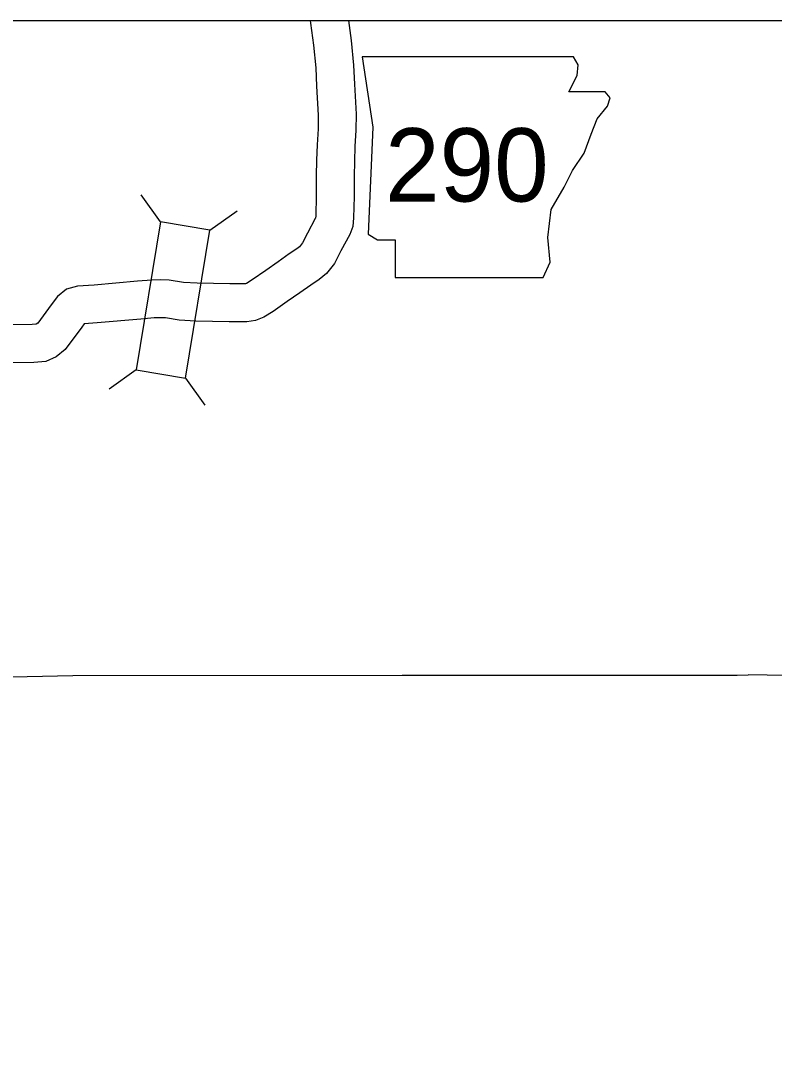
# Model space of a CAD drawing. Extents: x 1373862 to 1377080, y 1164775 to 1170415.
# Drawn here: x 1374349.9 to 1374409.6, y 1170307.2 to 1170388.8 of the extents above; entities that cross this region are included whole.
import ezdxf

# ---------------------------------------------------------------- set-up
doc = ezdxf.new("R2010")
doc.units = 0
doc.layers.add('1', color=7, linetype='Continuous')
doc.layers.add('Default', color=7, linetype='Continuous')

msp = doc.modelspace()

# ---------------------------------------------------------------- linework, layer by layer
at = {"layer": '1'}
msp.add_lwpolyline([(1373884.485, 1170388.771), (1374613.882, 1170388.771), (1374613.882, 1169861.944), (1373884.485, 1169861.944)], close=True, dxfattribs=at)
at = {"layer": 'Default'}
for p, q in [((1374361.035, 1170372.822), (1374359.499, 1170374.969)), ((1374364.942, 1170372.175), (1374367.089, 1170373.711)), ((1374359.092, 1170361.103), (1374356.945, 1170359.566)), ((1374362.998, 1170360.455), (1374364.534, 1170358.308))]:
    msp.add_line(p, q, dxfattribs=at)
for points in [[(1374372.884, 1170388.771), (1374372.899, 1170388.568), (1374373.145, 1170386.836), (1374373.315, 1170385.017), (1374373.385, 1170383.584), (1374373.516, 1170381.278), (1374373.503, 1170380.207), (1374373.423, 1170378.937), (1374373.389, 1170377.717), (1374373.356, 1170376.468), (1374373.349, 1170374.884), (1374373.314, 1170373.297), (1374373.3, 1170373.12), (1374373.285, 1170373.08), (1374372.668, 1170371.931), (1374372.26, 1170371.154), (1374372.02, 1170370.845), (1374371.821, 1170370.687), (1374371.224, 1170370.281), (1374370.352, 1170369.666), (1374369.356, 1170368.983), (1374368.284, 1170368.234), (1374367.823, 1170367.944), (1374367.76, 1170367.918), (1374367.651, 1170367.903), (1374366.506, 1170367.905), (1374363.939, 1170367.966), (1374362.835, 1170368.023), (1374361.716, 1170368.209), (1374361.009, 1170368.237), (1374360.346, 1170368.215), (1374359.209, 1170368.116), (1374355.761, 1170367.816), (1374354.457, 1170367.721), (1374353.583, 1170367.503), (1374352.858, 1170366.918), (1374352.371, 1170366.256), (1374351.305, 1170364.809), (1374351.182, 1170364.711), (1374350.853, 1170364.686), (1374347.914, 1170364.663)], [(1374375.901, 1170388.771), (1374376.126, 1170387.187), (1374376.309, 1170385.229), (1374376.381, 1170383.741), (1374376.517, 1170381.346), (1374376.502, 1170380.095), (1374376.42, 1170378.8), (1374376.388, 1170377.636), (1374376.356, 1170376.422), (1374376.349, 1170374.843), (1374376.311, 1170373.146), (1374376.257, 1170372.461), (1374376.022, 1170371.837), (1374375.317, 1170370.524), (1374374.793, 1170369.526), (1374374.17, 1170368.722), (1374373.6, 1170368.268), (1374372.931, 1170367.815), (1374372.065, 1170367.204), (1374371.064, 1170366.517), (1374369.943, 1170365.733), (1374369.197, 1170365.264), (1374368.546, 1170364.999), (1374367.858, 1170364.903), (1374366.468, 1170364.905), (1374363.825, 1170364.968), (1374362.511, 1170365.036), (1374361.41, 1170365.219), (1374360.999, 1170365.235), (1374360.525, 1170365.22), (1374359.469, 1170365.127), (1374356, 1170364.826), (1374354.988, 1170364.752), (1374354.787, 1170364.478), (1374353.484, 1170362.708), (1374352.76, 1170362.134), (1374351.945, 1170361.761), (1374350.979, 1170361.687), (1374347.951, 1170361.663)], [(1374486.683, 1170375.473), (1374486.464, 1170363.777), (1374486.093, 1170337.31), (1374459.219, 1170337.737), (1374433.196, 1170337.701), (1374433.113, 1170336.477), (1374407.559, 1170336.942)], [(1374326.295, 1170336.35), (1374327.589, 1170336.304), (1374354.076, 1170336.877), (1374380.161, 1170336.915), (1374406.695, 1170336.909), (1374407.559, 1170336.942)]]:
    msp.add_lwpolyline(points, dxfattribs=at)
for points in [[(1374376.993, 1170385.91), (1374377.83, 1170380.327), (1374377.458, 1170371.86), (1374378.202, 1170371.395), (1374379.598, 1170371.395), (1374379.598, 1170368.417), (1374391.322, 1170368.417), (1374391.88, 1170369.627), (1374391.694, 1170371.581), (1374391.974, 1170373.814), (1374392.997, 1170375.582), (1374393.648, 1170376.884), (1374394.579, 1170378.28), (1374395.137, 1170379.769), (1374395.602, 1170380.979), (1374396.44, 1170382.002), (1374396.626, 1170382.653), (1374396.254, 1170383.119), (1374393.369, 1170383.119), (1374394.021, 1170384.421), (1374394.114, 1170385.259), (1374393.728, 1170385.902)], [(1374362.998, 1170360.455), (1374364.942, 1170372.175), (1374361.035, 1170372.822), (1374359.092, 1170361.103)]]:
    msp.add_lwpolyline(points, close=True, dxfattribs=at)

# ---------------------------------------------------------------- texts
msp.add_text('290', height=5.808, dxfattribs=at).set_placement((1374378.811, 1170374.436))

doc.saveas('drawing.dxf')
